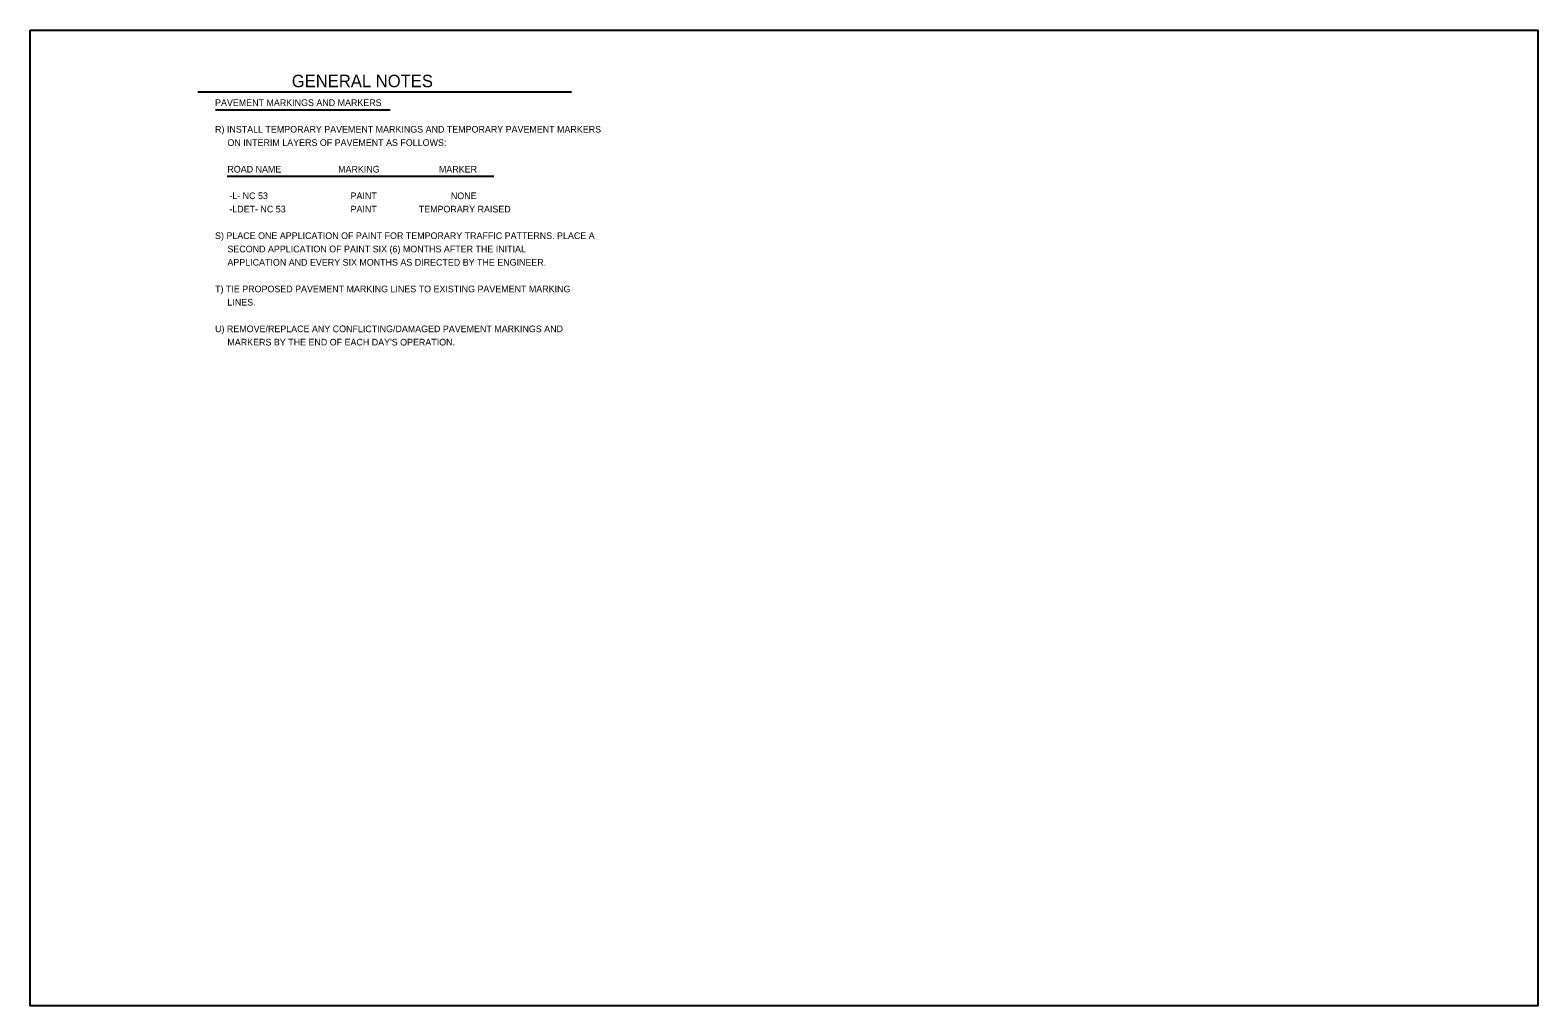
# Model space of a CAD drawing. Extents: x 0 to 3600, y 0 to 1100.
# Drawn here: x 1900 to 3600, y 0 to 1100 of the extents above; entities that cross this region are included whole.
import ezdxf

# ---------------------------------------------------------------- set-up
doc = ezdxf.new("R2010")
doc.units = 0
for name, color, linetype in [('DEV BORDER CELL', 7, 'Continuous'), ('Prop Grid Mask', 7, 'Continuous'), ('Sheet Plan CELL', 7, 'Continuous'), ('Sheet_Plan', 7, 'Continuous'), ('Sheet_RDY_XS_Number', 7, 'Continuous')]:
    doc.layers.add(name, color=color, linetype=linetype)

msp = doc.modelspace()

# ---------------------------------------------------------------- linework, layer by layer
at = {"layer": 'DEV BORDER CELL'}
msp.add_line((2089, 1030.3), (2510.4, 1030.3), dxfattribs=at)
at = {"layer": 'Sheet Plan CELL'}
msp.add_lwpolyline([(1900, 1100), (3600, 1100), (3600, 0), (1900, 0)], close=True, dxfattribs=at)
at = {"layer": 'Sheet_RDY_XS_Number'}
for p, q in [((2108.8, 1010.3), (2306, 1010.3)), ((2122.2, 935.3), (2422.9, 935.3))]:
    msp.add_line(p, q, dxfattribs=at)

# ---------------------------------------------------------------- texts
at = {"layer": 'Prop Grid Mask'}
for s, p in [('       PAVEMENT MARKINGS AND MARKERS', (2089, 1014.5)), ('       R) INSTALL TEMPORARY PAVEMENT MARKINGS AND TEMPORARY PAVEMENT MARKERS', (2089, 984.5)), ('            ON INTERIM LAYERS OF PAVEMENT AS FOLLOWS:', (2089, 969.5)), ('            ROAD NAME                       MARKING                        MARKER', (2089, 939.5)), ('  -L- NC 53', (2119, 909.5)), ('  -LDET- NC 53', (2119, 894.5)), ('        PAINT                              NONE', (2239, 909.5)), ('        PAINT                 TEMPORARY RAISED', (2239, 894.5)), ('       S) PLACE ONE APPLICATION OF PAINT FOR TEMPORARY TRAFFIC PATTERNS. PLACE A', (2089, 864.5)), ('            SECOND APPLICATION OF PAINT SIX (6) MONTHS AFTER THE INITIAL', (2089, 849.5)), ('            APPLICATION AND EVERY SIX MONTHS AS DIRECTED BY THE ENGINEER.', (2089, 834.5)), ('       T) TIE PROPOSED PAVEMENT MARKING LINES TO EXISTING PAVEMENT MARKING', (2089, 804.5)), ('            LINES.', (2089, 789.5)), ('       U) REMOVE/REPLACE ANY CONFLICTING/DAMAGED PAVEMENT MARKINGS AND   ', (2089, 759.5)), ("            MARKERS BY THE END OF EACH DAY'S OPERATION.", (2089, 744.5))]:
    msp.add_text(s, height=7.5, dxfattribs=at).set_placement(p)
at = {"layer": 'Sheet_Plan'}
msp.add_text('GENERAL NOTES', height=14, dxfattribs=at).set_placement((2195, 1035.7))

doc.saveas('drawing.dxf')
